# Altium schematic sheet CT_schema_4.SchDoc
size 469 x 430 mm
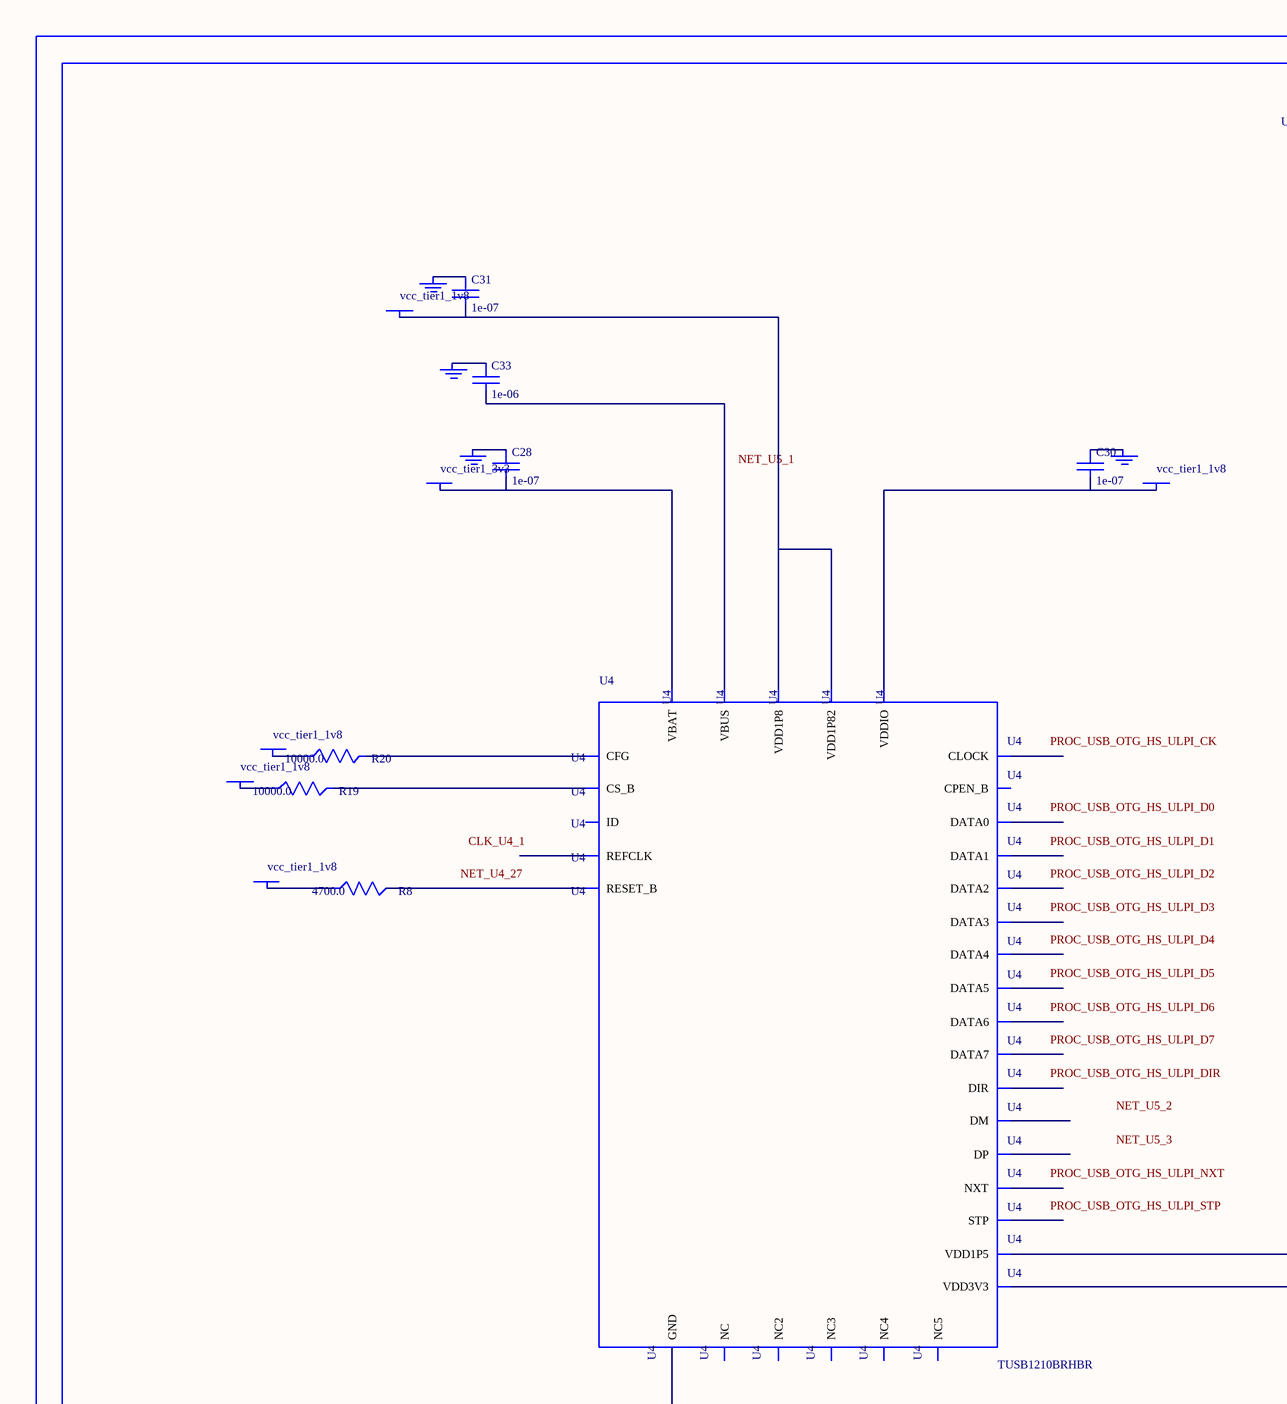
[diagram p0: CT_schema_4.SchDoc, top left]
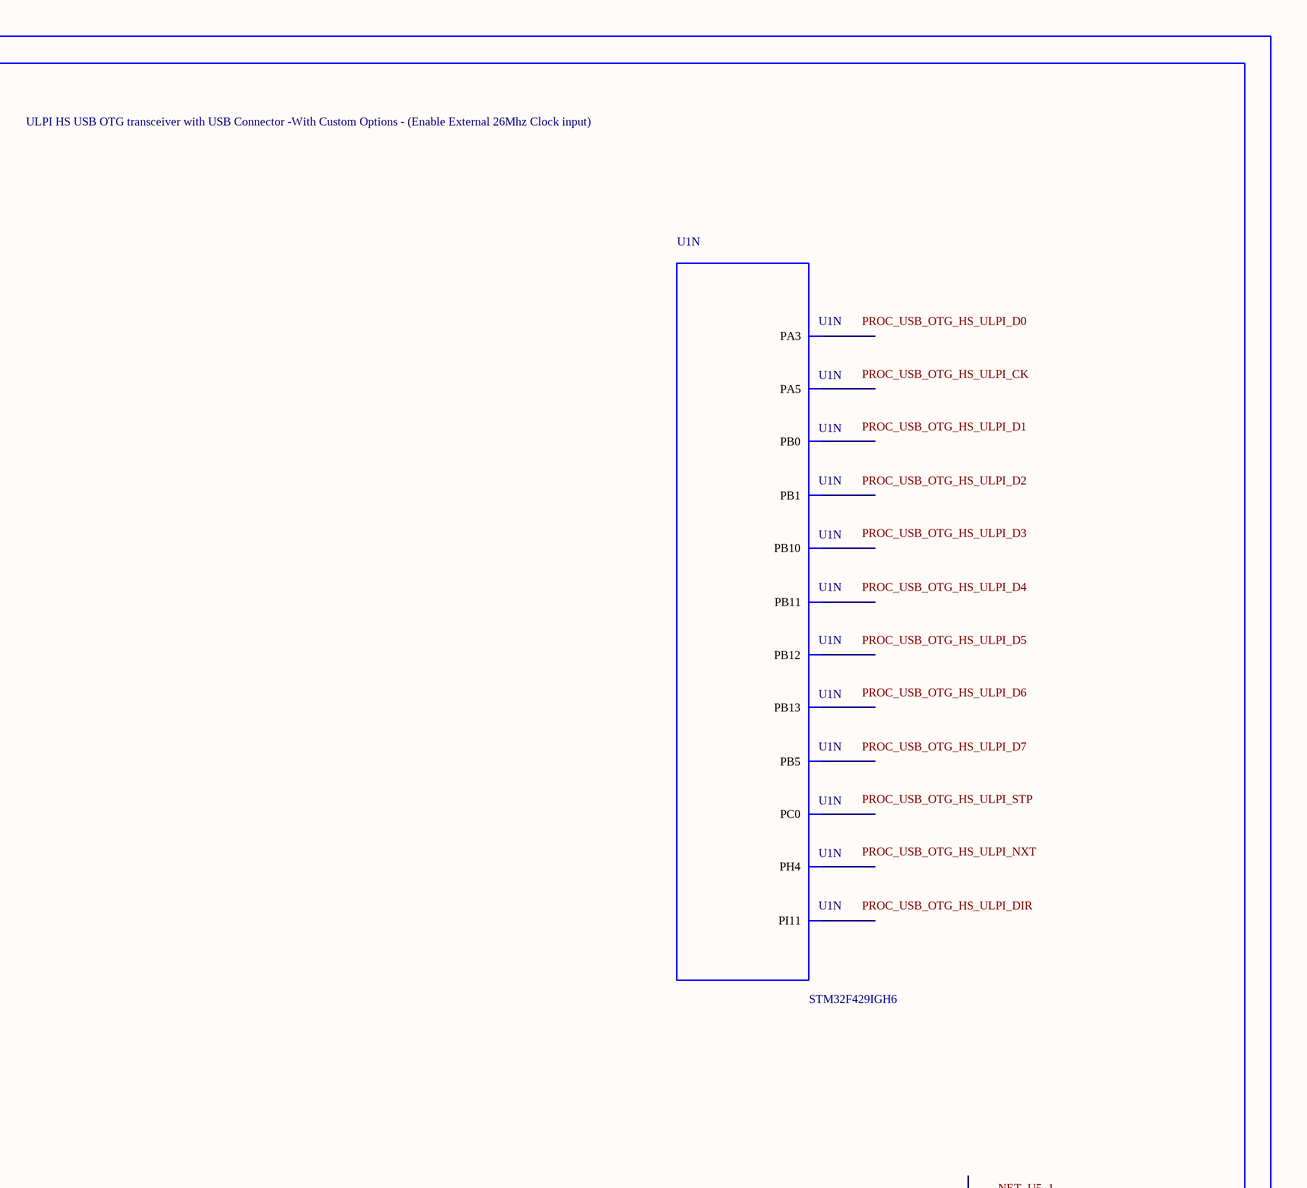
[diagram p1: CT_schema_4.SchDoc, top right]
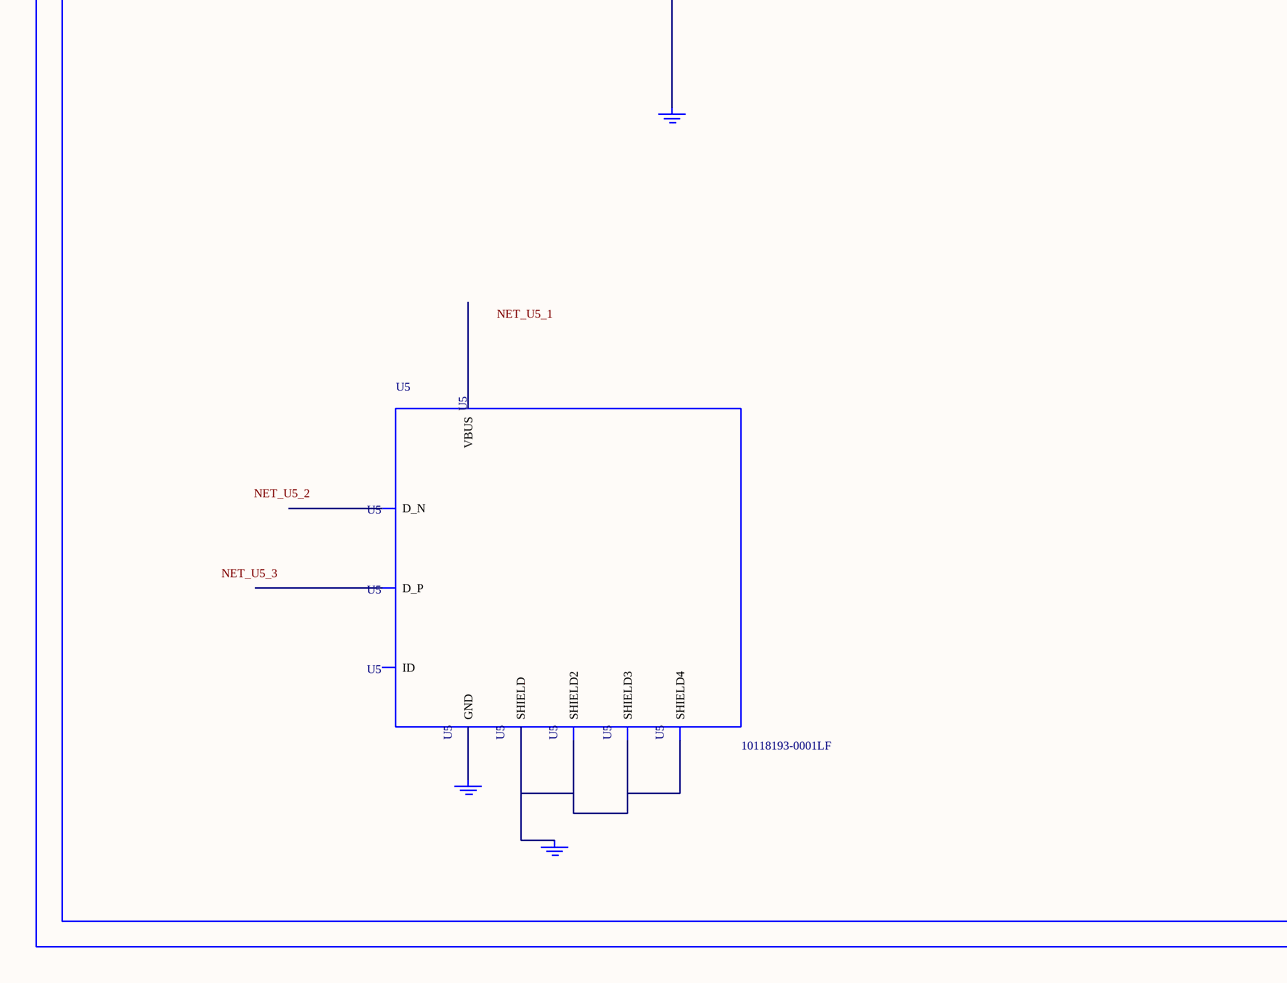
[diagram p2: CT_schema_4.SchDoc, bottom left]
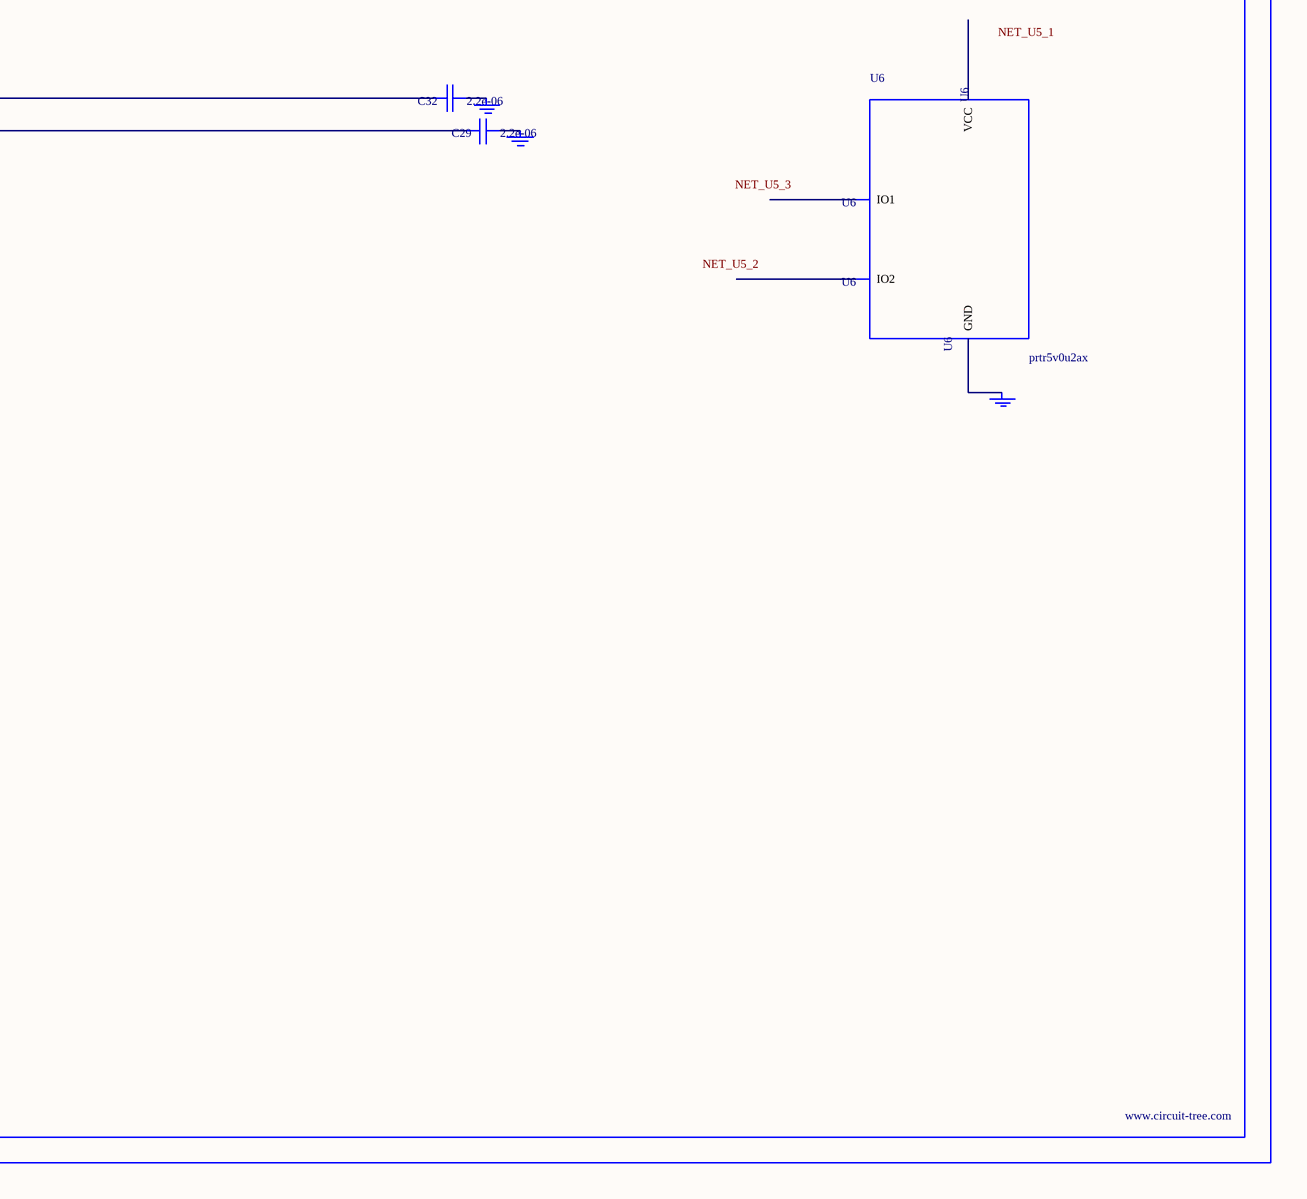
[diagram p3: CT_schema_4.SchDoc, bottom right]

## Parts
BORDER3  (no value)
C28  1e-07  [C0402]
C29  2.2e-06  [C0603]
C30  1e-07  [C0402]
C31  1e-07  [C0402]
C32  2.2e-06  [C0603]
C33  1e-06  [C0603]
GND_INSTANCE_3_0  (no value)
GND_INSTANCE_3_1  (no value)
GND_INSTANCE_3_2  (no value)
GND_INSTANCE_3_3  (no value)
GND_INSTANCE_3_4  (no value)
GND_INSTANCE_3_5  (no value)
GND_INSTANCE_3_6  (no value)
GND_INSTANCE_3_7  (no value)
GND_INSTANCE_3_8  (no value)
GND_INSTANCE_3_9  (no value)
POWER_INSTANCE_3_0  vcc_tier1_1v8
POWER_INSTANCE_3_1  vcc_tier1_1v8
POWER_INSTANCE_3_2  vcc_tier1_3v3
POWER_INSTANCE_3_3  vcc_tier1_1v8
POWER_INSTANCE_3_4  vcc_tier1_1v8
POWER_INSTANCE_3_5  vcc_tier1_1v8
R8  4700.0  [R0603]
R19  10000.0  [R0603]
R20  10000.0  [R0603]
U1  STM32F429IGH6  [UFBGA176_25]  (part N of 15)
U4  TUSB1210BRHBR  [RHB32_3P45X3P45]
U5  10118193-0001LF  [FCI_10118193-0001LF]
U6  prtr5v0u2ax  [SOT143B]

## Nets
NetC28_1: C28.1 GND_INSTANCE_3_2.0(GND)
NetC28_2: C28.2 POWER_INSTANCE_3_2.0(PWR) U4.21(VBAT)
NetC29_1: C29.1 GND_INSTANCE_3_1.0(GND)
NetC29_2: C29.2 U4.20(VDD3V3)
NetC30_1: C30.1 GND_INSTANCE_3_5.0(GND)
NetC30_2: C30.2 POWER_INSTANCE_3_4.0(PWR) U4.32(VDDIO)
NetC31_1: C31.1 GND_INSTANCE_3_4.0(GND)
NetC31_2: C31.2 POWER_INSTANCE_3_3.0(PWR) U4.28(VDD1P8) U4.30(VDD1P82)
NetC32_1: C32.1 GND_INSTANCE_3_0.0(GND)
NetC32_2: C32.2 U4.12(VDD1P5)
NetC33_1: C33.1 GND_INSTANCE_3_3.0(GND)
NetC33_2: C33.2 U4.22(VBUS)
NetGND_INSTANCE_3_6_0: GND_INSTANCE_3_6.0(GND) U4.33(GND)
NetGND_INSTANCE_3_7_0: GND_INSTANCE_3_7.0(GND) U5.6(SHIELD) U5.7(SHIELD2) U5.8(SHIELD3) U5.9(SHIELD4)
NetGND_INSTANCE_3_8_0: GND_INSTANCE_3_8.0(GND) U5.5(GND)
NetGND_INSTANCE_3_9_0: GND_INSTANCE_3_9.0(GND) U6.1(GND)
NetPOWER_INSTANCE_3_0_0: POWER_INSTANCE_3_0.0(PWR) R19.1
NetPOWER_INSTANCE_3_1_0: POWER_INSTANCE_3_1.0(PWR) R20.1
NetPOWER_INSTANCE_3_5_0: POWER_INSTANCE_3_5.0(PWR) R8.1
NetR8_2: R8.2 U4.27(RESET_B)
NetR19_2: R19.2 U4.11(CS_B)
NetR20_2: R20.2 U4.14(CFG)

Not connected (* = marked no-connect by the designer): U1 A6(PB5) E4(PI11) H4(PH4) M2(PC0) P4(PA5) P12(PB12) P13(PB13) R2(PA3) R4(PB1) R5(PB0) R12(PB10) R13(PB11); U4 1(REFCLK) 2(NXT) 3(DATA0) 4(DATA1) 5(DATA2) 6(DATA3) 7(DATA4) 8(NC) 9(DATA5) 10(DATA6) 13(DATA7) 15(NC2) 16(NC3) 17(CPEN_B) 18(DP) 19(DM) 23(ID) 24(NC4) 25(NC5) 26(CLOCK) 29(STP) 31(DIR); U5 1(VBUS) 2(D_N) 3(D_P) 4(ID); U6 2(IO1) 3(IO2) 4(VCC)

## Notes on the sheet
- Labels drawn without touching a wire or pin: CLK_U4_1, NET_U4_27, NET_U5_1, NET_U5_2, NET_U5_3, PROC_USB_OTG_HS_ULPI_CK, PROC_USB_OTG_HS_ULPI_D0, PROC_USB_OTG_HS_ULPI_D1, PROC_USB_OTG_HS_ULPI_D2, PROC_USB_OTG_HS_ULPI_D3, PROC_USB_OTG_HS_ULPI_D4, PROC_USB_OTG_HS_ULPI_D5, PROC_USB_OTG_HS_ULPI_D6, PROC_USB_OTG_HS_ULPI_D7, PROC_USB_OTG_HS_ULPI_DIR, PROC_USB_OTG_HS_ULPI_NXT, PROC_USB_OTG_HS_ULPI_STP

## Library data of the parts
BORDER3 = BORDER_PAGE3
C28 C30 C31 = C0402C104K3RACTU
C29 C32 = C0603C225K8RACTU
C33 = C0603C105K3RACTU
GND_INSTANCE_3_0-GND_INSTANCE_3_9 = GND
POWER_INSTANCE_3_0-POWER_INSTANCE_3_5 = PWR
R8 = RC0603JR-074K7L
R19 R20 = RC0603JR-0710KL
